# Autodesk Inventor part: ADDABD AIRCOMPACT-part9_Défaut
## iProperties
Shininess: 64.0
Length Units: 11269
Angle Units: 11279
Time Units: 11290
Mass Units: 11283
Length Display Precision: 3
Angle Display Precision: 2
Compacted: True
Part Number: ADDABD AIRCOMPACT-part9_Défaut
Document SubType Name: Modeling
Created: 2006-01
Material: Par défaut
Designer: riri
Density: 0.0
Volumn: 0.0
Area: 0.0
PropertySet Name: Model Information
Control State: 0
Master: False
Checked Out: False
Author: riri
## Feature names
1. Base1
